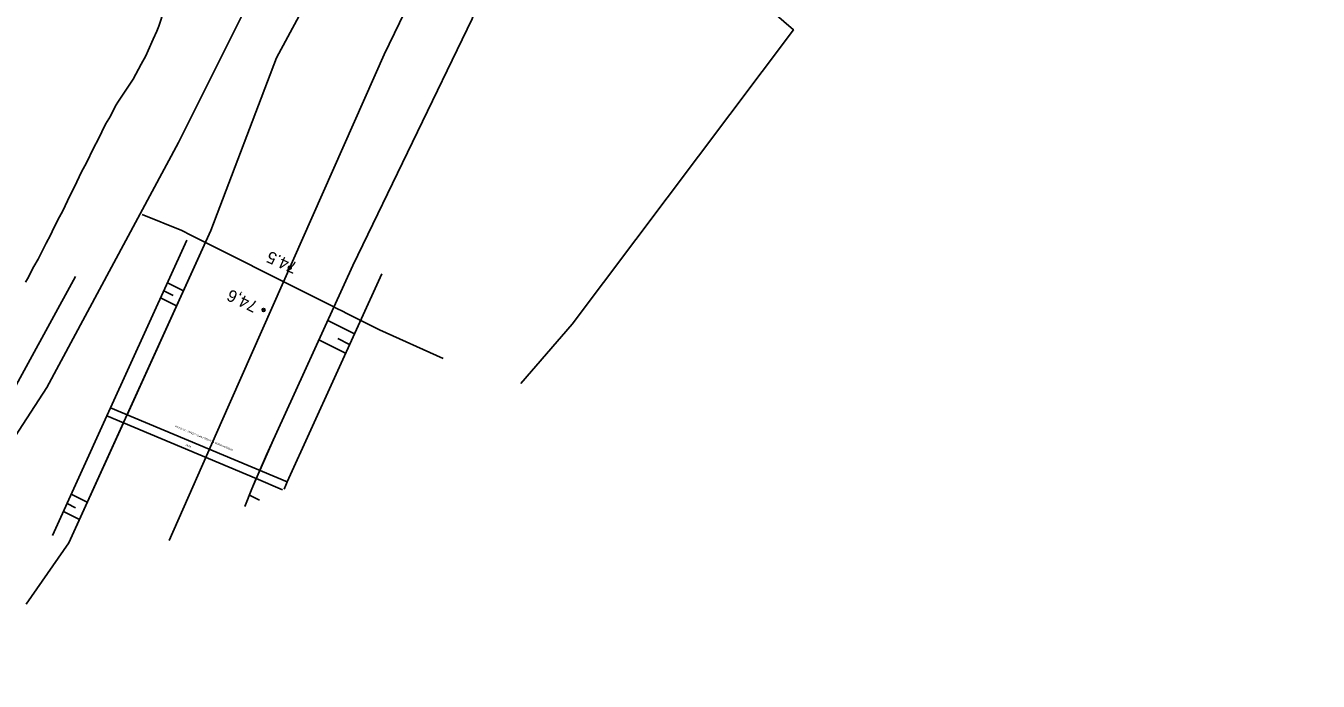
# Model space of a CAD drawing. Extents: x -737422 to -734235, y -1145631 to -1142623.
# Drawn here: x -735933.5 to -735717.2, y -1144069.2 to -1143959.5 of the extents above; entities that cross this region are included whole.
import ezdxf

# ---------------------------------------------------------------- set-up
doc = ezdxf.new("R2010")
doc.units = 0
for name, color, linetype in [('Vrstva 1', 7, 'Continuous'), ('Vrstva 2', 7, 'Continuous'), ('Vrstva 20', 7, 'Continuous'), ('Vrstva 21', 7, 'Continuous'), ('Vrstva 22', 7, 'Continuous'), ('Vrstva 3', 7, 'Continuous'), ('Vrstva 30', 7, 'Continuous'), ('Vrstva 6', 7, 'Continuous'), ('Vrstva 7', 7, 'Continuous'), ('Vrstva 8', 7, 'Continuous')]:
    doc.layers.add(name, color=color, linetype=linetype)

# ---------------------------------------------------------------- blocks, each defined once
blk = doc.blocks.new('1.050')
at = {"layer": 'Vrstva 1'}
for radius in [0.5, 0.001]:
    blk.add_circle((0, 0), radius, dxfattribs=at)

msp = doc.modelspace()

# ---------------------------------------------------------------- linework, layer by layer
at = {"layer": 'Vrstva 1'}
for points in [[(-735850.673, -1144019.327), (-735842.07, -1144009.45), (-735805.02, -1143960.16), (-735816.73, -1143950.02)], [(-735910.346, -1143956.824), (-735911.241, -1143959.529), (-735911.578, -1143960.392), (-735912.221, -1143961.749), (-735913.033, -1143963.604), (-735913.463, -1143964.507), (-735914.235, -1143965.893), (-735915.101, -1143967.589), (-735915.563, -1143968.406), (-735918.043, -1143972.085), (-735918.503, -1143972.906), (-735919.381, -1143974.589), (-735920.17, -1143975.959), (-735921.427, -1143978.543), (-735922.139, -1143979.831), (-735923.431, -1143982.539), (-735924.138, -1143983.832), (-735925.425, -1143986.545), (-735926.132, -1143987.838), (-735927.419, -1143990.55), (-735928.127, -1143991.843), (-735929.112, -1143993.937), (-735929.418, -1143994.552), (-735930.129, -1143995.841), (-735931.439, -1143998.53), (-735932.171, -1143999.799), (-735933.225, -1144001.824), (-735933.562, -1144002.408)]]:
    msp.add_lwpolyline(points, dxfattribs=at)
at = {"layer": 'Vrstva 2'}
msp.add_lwpolyline([(-735809.77, -1143882.86), (-735838.15, -1143907.13), (-735842.51, -1143912.31), (-735856.42, -1143928.85), (-735873.56, -1143964.3), (-735900.76, -1144025.76), (-735909.535, -1144045.615)], dxfattribs=at)
at = {"layer": 'Vrstva 20'}
for points in [[(-735902.54, -1143993.73), (-735916.57, -1144024.57)], [(-735906.58, -1143995.37), (-735919.33, -1144023.41), (-735919.96, -1144024.77), (-735929.05, -1144044.77)], [(-735878.8, -1143999.61), (-735893.22, -1144031.3)], [(-735873.93, -1144000.98), (-735889.79, -1144035.83), (-735890.03, -1144036.36)], [(-735919.96, -1144024.77), (-735917.19, -1144025.93), (-735894.96, -1144035.28), (-735890.548, -1144037.135)], [(-735919.33, -1144023.41), (-735889.79, -1144035.83)], [(-735917.19, -1144025.93), (-735926.32, -1144046.01)], [(-735894.38, -1144033.89), (-735891.89, -1144028.32)], [(-735895.67, -1144037), (-735894.96, -1144035.28)], [(-735896.841, -1144039.946), (-735895.67, -1144037)], [(-735890.295, -1144037.022), (-735890.03, -1144036.36)]]:
    msp.add_lwpolyline(points, dxfattribs=at)
at = {"layer": 'Vrstva 21'}
for points in [[(-735909.82, -1144002.5), (-735907.14, -1144003.84)], [(-735910.97, -1144005.03), (-735908.29, -1144006.37)], [(-735910.42, -1144003.82), (-735908.85, -1144004.6)], [(-735882.98, -1144008.79), (-735878.38, -1144011.08)], [(-735884.47, -1144012.06), (-735879.99, -1144014.3)], [(-735881.29, -1144011.83), (-735879.32, -1144012.82)], [(-735925.93, -1144037.89), (-735923.24, -1144039.23)], [(-735896.08, -1144038.03), (-735894.413, -1144038.861)], [(-735926.62, -1144039.42), (-735925.2, -1144040.14)], [(-735927.25, -1144040.8), (-735924.56, -1144042.14)]]:
    msp.add_lwpolyline(points, dxfattribs=at)
at = {"layer": 'Vrstva 3'}
for points in [[(-735717.18, -1143825.059), (-735728.72, -1143828.2), (-735767.75, -1143842.4), (-735794, -1143856.95), (-735813.38, -1143868.5), (-735839.26, -1143889.51), (-735849.9, -1143899.22), (-735862.74, -1143913.68), (-735864.22, -1143916.19), (-735877.51, -1143938.72), (-735891.56, -1143964.83), (-735902.54, -1143993.73), (-735926.32, -1144046.01), (-735933.469, -1144056.304)], [(-735896.841, -1144039.946), (-735895.67, -1144037), (-735893.22, -1144031.3), (-735878.8, -1143999.61), (-735858.83, -1143958.3), (-735853.98, -1143945.05)]]:
    msp.add_lwpolyline(points, dxfattribs=at)
at = {"layer": 'Vrstva 30'}
for points in [[(-735959.949, -1144068.13), (-735956, -1144060), (-735930, -1144020), (-735908, -1143979), (-735884, -1143931), (-735875, -1143917), (-735872, -1143913)], [(-735925.19, -1144001.43), (-735962.274, -1144069.168)]]:
    msp.add_lwpolyline(points, dxfattribs=at)
at = {"layer": 'Vrstva 8'}
msp.add_lwpolyline([(-735914.06, -1143991.05), (-735907.44, -1143993.77), (-735905.9, -1143994.54), (-735903.36, -1143995.81), (-735899.09, -1143997.95), (-735892.11, -1144001.45), (-735885.18, -1144004.92), (-735882.44, -1144006.3), (-735881.13, -1144006.95), (-735880.86, -1144007.09), (-735879.48, -1144007.78), (-735876.89, -1144009.08), (-735874.31, -1144010.37), (-735863.65, -1144015.15)], dxfattribs=at)

# ---------------------------------------------------------------- block references
at = {"layer": 'Vrstva 6', "xscale": 0.5, "yscale": 0.5}
for p in [(-735889.35, -1143999.97), (-735893.74, -1144007.05)]:
    msp.add_blockref('1.050', p, dxfattribs=at)

# ---------------------------------------------------------------- texts
at = {"layer": 'Vrstva 22'}
for s, rotation, p in [('PRODUKTOVOD VE VESELÍ NAD LUŽNICÍ - 74,625 km', 157.49, (-735898.81, -1144030.36)), ('lávka', 338.965, (-735906.81, -1144029.74))]:
    msp.add_text(s, height=0.3, rotation=rotation, dxfattribs=at).set_placement(p)
at = {"layer": 'Vrstva 7'}
for s, rotation, p in [('  74.5', 156.13, (-735886.53, -1143999.83)), ('74,6', 154.536, (-735894.53, -1144005.76))]:
    msp.add_text(s, height=2, rotation=rotation, dxfattribs=at).set_placement(p)

doc.saveas('drawing.dxf')
